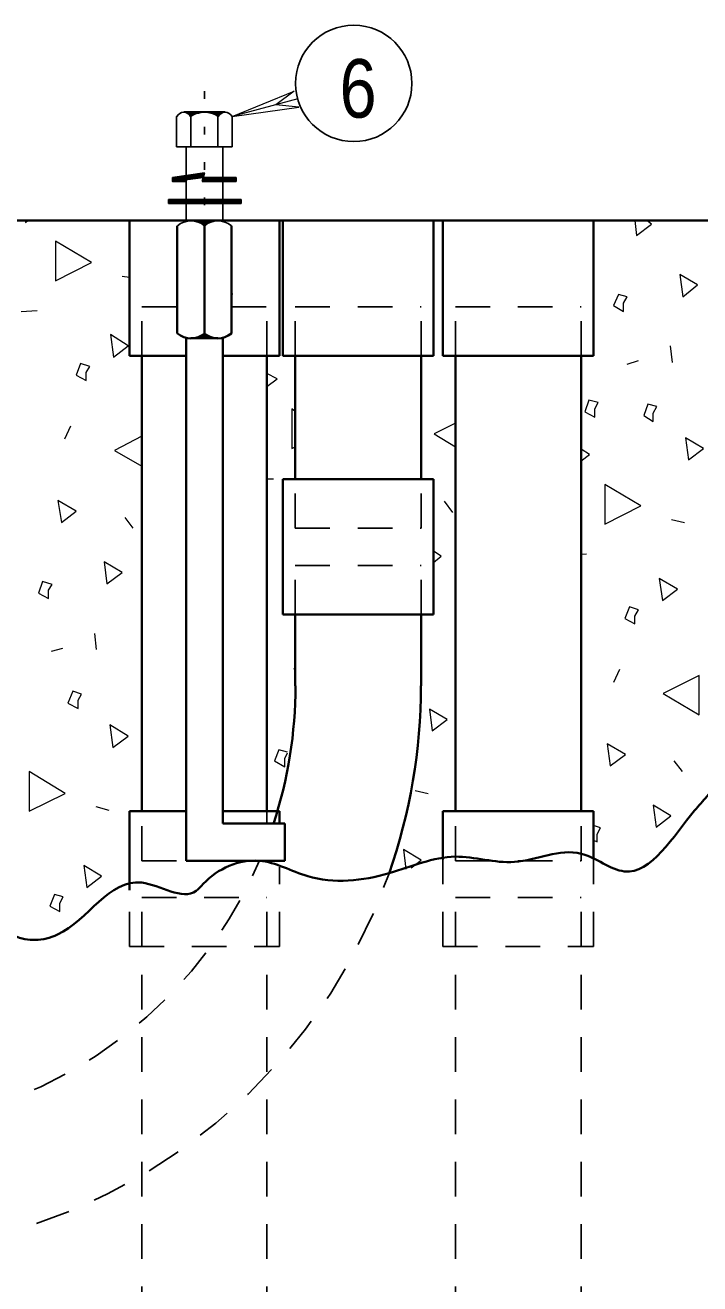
# Model space of a CAD drawing. Extents: x 312583 to 312854, y 144419 to 144597.
# Drawn here: x 312689.79 to 312698.55, y 144530.8 to 144547.14 of the extents above; entities that cross this region are included whole.
import ezdxf

# ---------------------------------------------------------------- set-up
doc = ezdxf.new("R2010")
doc.units = 0
doc.header["$LTSCALE"] = 0.3
doc.linetypes.add('DOTTED', pattern=[1.5, 0.3, -1.2])
doc.linetypes.add('SHORT_DASHED', pattern=[2.7, 1.5, -1.2])
doc.layers.add('1', color=7, linetype='Continuous', lineweight=25)
doc.layers.add('2', color=7, linetype='Continuous', lineweight=13)

msp = doc.modelspace()

# ---------------------------------------------------------------- linework, layer by layer
at = {"layer": '1', "linetype": 'DOTTED'}
msp.add_line((312692.1154, 144546.2789), (312692.1154, 144544.5999), dxfattribs=at)
at = {"layer": '1'}
for p, q in [((312691.7551, 144545.9493), (312691.7551, 144545.5583)), ((312691.8471, 144546.0106), (312692.3837, 144546.0106)), ((312691.9391, 144545.9493), (312691.9391, 144545.5583)), ((312692.2917, 144545.9493), (312692.2917, 144545.5583)), ((312692.4757, 144545.9493), (312692.4757, 144545.5583)), ((312691.7551, 144545.5583), (312692.4757, 144545.5583)), ((312691.8777, 144545.5583), (312691.8777, 144544.5999)), ((312692.3531, 144545.5583), (312692.3531, 144544.5999)), ((312691.7014, 144545.1596), (312691.7014, 144545.1059)), ((312692.0847, 144545.1059), (312692.5294, 144545.1059)), ((312692.1001, 144545.1596), (312692.5294, 144545.1596)), ((312692.5294, 144545.1596), (312692.5294, 144545.1059)), ((312691.6477, 144544.8759), (312692.5907, 144544.8759)), ((312691.6477, 144544.8759), (312691.6477, 144544.8223)), ((312692.5907, 144544.8759), (312692.5907, 144544.8223)), ((312691.6477, 144544.8683), (312692.5907, 144544.8683)), ((312691.6477, 144544.8529), (312692.5907, 144544.8529)), ((312691.6477, 144544.8376), (312692.5907, 144544.8376)), ((312691.6477, 144544.8223), (312692.5907, 144544.8223)), ((312691.8777, 144544.5999), (312692.3531, 144544.5999)), ((312691.9391, 144544.5999), (312692.2917, 144544.5999))]:
    msp.add_line(p, q, dxfattribs=at)
at = {"layer": '1', "lineweight": 40}
for p, q in [((312656.9791, 144544.5999), (312705.5321, 144544.5999)), ((312691.1417, 144542.8443), (312691.1417, 144544.5999)), ((312692.1154, 144544.5999), (312692.1154, 144543.0743)), ((312693.0891, 144542.8443), (312693.0891, 144544.5999)), ((312693.1351, 144542.8443), (312693.1351, 144544.5999)), ((312695.0901, 144542.8443), (312695.0901, 144544.5999)), ((312695.2127, 144542.8443), (312695.2127, 144544.5999)), ((312697.1677, 144542.8443), (312697.1677, 144544.5999)), ((312691.7627, 144544.5309), (312691.7627, 144543.1356)), ((312692.4681, 144544.5309), (312692.4681, 144543.1356)), ((312691.8777, 144543.0743), (312691.8777, 144536.2893)), ((312691.9391, 144543.0743), (312692.2917, 144543.0743)), ((312692.3531, 144543.0743), (312692.3531, 144536.7723)), ((312691.1417, 144542.8443), (312691.8777, 144542.8443)), ((312691.3027, 144536.9333), (312691.3027, 144542.8443)), ((312692.3531, 144542.8443), (312693.0891, 144542.8443)), ((312692.9281, 144536.9333), (312692.9281, 144542.8443)), ((312693.1351, 144542.8443), (312695.0901, 144542.8443)), ((312693.2961, 144541.2419), (312693.2961, 144542.8443)), ((312694.9291, 144541.2419), (312694.9291, 144542.8443)), ((312695.2127, 144542.8443), (312697.1677, 144542.8443)), ((312695.3737, 144536.9333), (312695.3737, 144542.8443)), ((312697.0067, 144536.9333), (312697.0067, 144542.8443)), ((312693.1351, 144539.4863), (312693.1351, 144541.2419)), ((312693.1351, 144541.2419), (312695.0901, 144541.2419)), ((312695.0901, 144539.4863), (312695.0901, 144541.2419)), ((312693.1351, 144539.4863), (312695.0901, 144539.4863)), ((312693.2961, 144538.5586), (312693.2961, 144539.4863)), ((312694.9291, 144538.5586), (312694.9291, 144539.4863)), ((312691.1417, 144536.9333), (312691.8777, 144536.9333)), ((312691.1417, 144535.9059), (312691.1417, 144536.9333)), ((312692.3531, 144536.9333), (312693.0891, 144536.9333)), ((312693.0891, 144536.7723), (312693.0891, 144536.9333)), ((312695.2127, 144536.9333), (312697.1677, 144536.9333)), ((312695.2127, 144536.3046), (312695.2127, 144536.9333)), ((312697.1677, 144536.3123), (312697.1677, 144536.9333)), ((312692.3531, 144536.7723), (312693.1581, 144536.7723)), ((312693.1581, 144536.7723), (312693.1581, 144536.2893)), ((312691.8777, 144536.2893), (312693.1581, 144536.2893))]:
    msp.add_line(p, q, dxfattribs=at)
at = {"layer": '1', "lineweight": 13}
msp.add_line((312692.4681, 144543.6493), (312692.4834, 144543.6493), dxfattribs=at)
at = {"layer": '1', "linetype": 'SHORT_DASHED'}
for p, q in [((312691.3027, 144542.8443), (312691.3027, 144543.4806)), ((312691.3027, 144543.4806), (312691.7627, 144543.4806)), ((312692.4681, 144543.4806), (312692.9281, 144543.4806)), ((312692.9281, 144542.8443), (312692.9281, 144543.4806)), ((312693.2961, 144543.4806), (312694.9291, 144543.4806)), ((312693.2961, 144542.8443), (312693.2961, 144543.4806)), ((312694.9291, 144542.8443), (312694.9291, 144543.4806)), ((312695.3737, 144543.4806), (312697.0067, 144543.4806)), ((312695.3737, 144542.8443), (312695.3737, 144543.4806)), ((312697.0067, 144542.8443), (312697.0067, 144543.4806)), ((312693.2961, 144540.6056), (312693.2961, 144541.2419)), ((312694.9291, 144540.6056), (312694.9291, 144541.2419)), ((312693.2961, 144540.6056), (312694.9291, 144540.6056)), ((312693.2961, 144540.1226), (312694.9291, 144540.1226)), ((312693.2961, 144539.4863), (312693.2961, 144540.1226)), ((312694.9291, 144539.4863), (312694.9291, 144540.1226)), ((312691.3027, 144536.2893), (312691.3027, 144536.9333)), ((312692.9281, 144536.7723), (312692.9281, 144536.9333)), ((312695.3737, 144536.2893), (312695.3737, 144536.9333)), ((312697.0067, 144536.2893), (312697.0067, 144536.9333)), ((312691.3027, 144536.2893), (312691.8777, 144536.2893)), ((312692.3531, 144536.2893), (312692.9281, 144536.2893)), ((312695.2127, 144535.1776), (312695.2127, 144536.3046)), ((312695.3737, 144536.2893), (312697.0067, 144536.2893)), ((312697.1677, 144535.1776), (312697.1677, 144536.3123)), ((312693.0891, 144535.1776), (312693.0891, 144536.2049)), ((312691.1417, 144535.1776), (312691.1417, 144535.9059)), ((312691.3027, 144535.1776), (312691.3027, 144535.8139)), ((312691.3027, 144535.8139), (312692.9281, 144535.8139)), ((312692.9281, 144535.1776), (312692.9281, 144535.8139)), ((312695.3737, 144535.8139), (312697.0067, 144535.8139)), ((312695.3737, 144535.1776), (312695.3737, 144535.8139)), ((312697.0067, 144535.1776), (312697.0067, 144535.8139)), ((312691.1417, 144535.1776), (312693.0891, 144535.1776)), ((312691.3027, 144523.8309), (312691.3027, 144535.1776)), ((312692.9281, 144523.8309), (312692.9281, 144535.1776)), ((312695.2127, 144535.1776), (312697.1677, 144535.1776)), ((312695.3737, 144523.8309), (312695.3737, 144535.1776)), ((312697.0067, 144523.8309), (312697.0067, 144535.1776))]:
    msp.add_line(p, q, dxfattribs=at)
at = {"layer": '1'}
for points in [[(312691.8701, 144546.0029), (312692.0694, 144546.0029), (312692.0387, 144545.9953), (312692.0157, 144545.9953), (312691.9774, 144545.9799), (312691.9391, 144545.9569), (312691.9237, 144545.9799), (312691.9084, 144545.9876), (312691.8777, 144546.0029), (312692.0541, 144546.0029), (312692.0081, 144545.9953), (312691.9697, 144545.9799), (312691.9391, 144545.9569), (312691.9084, 144545.9876), (312691.8931, 144546.0029), (312692.0311, 144546.0029), (312691.9851, 144545.9876), (312691.9391, 144545.9646), (312691.9007, 144545.9953), (312692.0157, 144546.0029), (312691.9391, 144545.9723), (312691.9084, 144545.9953), (312692.0004, 144545.9953), (312691.9391, 144545.9723), (312691.9161, 144545.9953), (312691.9927, 144545.9953), (312691.9391, 144545.9799), (312691.9237, 144545.9953), (312691.9697, 144545.9953), (312691.9391, 144545.9799), (312691.9314, 144545.9876), (312691.9544, 144545.9876), (312691.9391, 144545.9876)], [(312692.3607, 144546.0029), (312692.1614, 144546.0029), (312692.1997, 144545.9953), (312692.2151, 144545.9953), (312692.2534, 144545.9799), (312692.2917, 144545.9569), (312692.3071, 144545.9799), (312692.3224, 144545.9876), (312692.3531, 144546.0029), (312692.1767, 144546.0029), (312692.2304, 144545.9953), (312692.2611, 144545.9799), (312692.2917, 144545.9569), (312692.3224, 144545.9876), (312692.3377, 144546.0029), (312692.1997, 144546.0029), (312692.2457, 144545.9876), (312692.2917, 144545.9646), (312692.3301, 144545.9953), (312692.2151, 144546.0029), (312692.2917, 144545.9723), (312692.3224, 144545.9953), (312692.2304, 144545.9953), (312692.2994, 144545.9723), (312692.3147, 144545.9953), (312692.2457, 144545.9953), (312692.2917, 144545.9799), (312692.3071, 144545.9953), (312692.2611, 144545.9953), (312692.2917, 144545.9799), (312692.2994, 144545.9876), (312692.2764, 144545.9876), (312692.2917, 144545.9876)], [(312691.7014, 144545.1596), (312692.1154, 144545.2209), (312692.0847, 144545.1059)], [(312691.8777, 144545.1059), (312691.7014, 144545.1136), (312691.7091, 144545.1596), (312692.1077, 144545.2056), (312692.0924, 144545.1673), (312691.8777, 144545.1366), (312691.8701, 144545.1136), (312691.7091, 144545.1213), (312691.7167, 144545.1519), (312692.0924, 144545.1979), (312692.0847, 144545.1749), (312691.8624, 144545.1366), (312691.8624, 144545.1213), (312691.7167, 144545.1213), (312691.7167, 144545.1366), (312692.0771, 144545.1903), (312692.0771, 144545.1826), (312691.8701, 144545.1443), (312691.8547, 144545.1366), (312691.8087, 144545.1289), (312691.7244, 144545.1289), (312692.0694, 144545.1826), (312691.7781, 144545.1289)], [(312692.1001, 144545.1596), (312691.7014, 144545.1059), (312691.8777, 144545.1059)], [(312692.0924, 144545.1136), (312692.5217, 144545.1136), (312692.5217, 144545.1596), (312692.1077, 144545.1519), (312692.0924, 144545.1213), (312692.5141, 144545.1213), (312692.5141, 144545.1443), (312692.1077, 144545.1443), (312692.1001, 144545.1213), (312692.5064, 144545.1289), (312692.4987, 144545.1366), (312692.4987, 144545.1443), (312692.1154, 144545.1366), (312692.1077, 144545.1289), (312692.4987, 144545.1289)], [(312691.9851, 144544.5923), (312692.2457, 144544.5923), (312692.2151, 144544.5923), (312692.1921, 144544.5846), (312692.1614, 144544.5693), (312692.1461, 144544.5616), (312692.1154, 144544.5463), (312692.1154, 144544.5386), (312692.0694, 144544.5693), (312692.0234, 144544.5846), (312692.0004, 144544.5923), (312692.2304, 144544.5923), (312692.2074, 144544.5923), (312692.1921, 144544.5846), (312692.1614, 144544.5769), (312692.1307, 144544.5616), (312692.1231, 144544.5539), (312692.1154, 144544.5463), (312692.0694, 144544.5693), (312692.0234, 144544.5923), (312692.1921, 144544.5923), (312692.1537, 144544.5769), (312692.1154, 144544.5539), (312692.0387, 144544.5846), (312692.1767, 144544.5923), (312692.1154, 144544.5463), (312692.0541, 144544.5846), (312692.1691, 144544.5846), (312692.1231, 144544.5616), (312692.0771, 144544.5846), (312692.1461, 144544.5846), (312692.1154, 144544.5693), (312692.0771, 144544.5769), (312692.1001, 144544.5616), (312692.1077, 144544.5769), (312692.1154, 144544.5539), (312692.1307, 144544.5769), (312692.1384, 144544.5769), (312692.1537, 144544.5769)]]:
    msp.add_lwpolyline(points, dxfattribs=at)
at = {"layer": '1', "lineweight": 40}
msp.add_lwpolyline([(312691.9851, 144543.0743), (312692.2457, 144543.0743), (312692.2151, 144543.0819), (312692.1921, 144543.0896), (312692.1614, 144543.0973), (312692.1461, 144543.1126), (312692.1154, 144543.1279), (312692.1154, 144543.1279), (312692.0694, 144543.0973), (312692.0234, 144543.0819), (312692.0004, 144543.0743), (312692.2304, 144543.0743), (312692.2074, 144543.0743), (312692.1921, 144543.0819), (312692.1614, 144543.0896), (312692.1307, 144543.1049), (312692.1231, 144543.1126), (312692.1154, 144543.1279), (312692.0694, 144543.0973), (312692.0234, 144543.0743), (312692.1921, 144543.0743), (312692.1537, 144543.0896), (312692.1154, 144543.1126), (312692.0387, 144543.0819), (312692.1767, 144543.0819), (312692.1154, 144543.1203), (312692.0541, 144543.0819), (312692.1691, 144543.0819), (312692.1231, 144543.1049), (312692.0771, 144543.0896), (312692.1461, 144543.0896), (312692.1154, 144543.0973), (312692.0771, 144543.0896), (312692.1001, 144543.1049), (312692.1077, 144543.0896), (312692.1154, 144543.1126), (312692.1307, 144543.0973), (312692.1384, 144543.0896), (312692.1537, 144543.0896)], dxfattribs=at)
at = {"layer": '1'}
for centre, radius, start, end in [((312691.8474, 144545.9078), 0.0993, 25.60064, 154.39936), ((312692.116, 144545.6945), 0.3126, 55.04559, 124.95441), ((312692.3847, 144545.9078), 0.0993, 25.60064, 154.39936), ((312691.9412, 144544.3253), 0.272, 50.00693, 129.99306), ((312692.2908, 144544.3253), 0.272, 50.00694, 129.99307)]:
    msp.add_arc(centre, radius, start, end, dxfattribs=at)
at = {"layer": '1', "lineweight": 40}
for centre, radius, start, end in [((312691.9412, 144543.3426), 0.272, 230.00694, 309.99307), ((312692.2908, 144543.3426), 0.272, 230.00693, 309.99306), ((312687.548, 144538.5599), 5.75, 341.8604, 0), ((312687.548, 144538.5599), 7.3792, 340.73599, 0)]:
    msp.add_arc(centre, radius, start, end, dxfattribs=at)
at = {"layer": '1', "linetype": 'SHORT_DASHED'}
for radius, end in [(5.75, 336.76867), (7.3792, 340.7336)]:
    msp.add_arc((312687.548, 144538.5599), radius, 270, end, dxfattribs=at)
at = {"layer": '1', "lineweight": 40}
msp.add_spline([(312699.3604, 144544.5999), (312699.8664, 144543.7259), (312700.4721, 144542.8443), (312700.1194, 144541.7709), (312699.5521, 144541.3263), (312699.2991, 144540.4139), (312699.1764, 144538.1983), (312698.6397, 144537.1249), (312698.4787, 144536.9409), (312697.5664, 144536.1513), (312697.0067, 144536.3813), (312696.1404, 144536.2739), (312695.3737, 144536.3429), (312694.5151, 144536.1283), (312693.4571, 144536.0899), (312692.8284, 144536.2893), (312692.1001, 144535.9903), (312692.0081, 144535.8983), (312691.3027, 144536.0056), (312690.2064, 144535.3309), (312689.9227, 144535.2619), (312688.8571, 144535.8293), (312687.2624, 144535.9059), (312686.9251, 144535.4459)], degree=3, dxfattribs=at)
at = {"layer": '2'}
for p, q in [((312692.4757, 144545.9493), (312693.2807, 144546.2789)), ((312693.3267, 144546.1793), (312692.4757, 144545.9493)), ((312693.2807, 144546.2789), (312693.0431, 144546.1026)), ((312692.4757, 144545.9493), (312693.3421, 144546.0719)), ((312693.3421, 144546.0719), (312693.0431, 144546.1026)), ((312689.7924, 144544.5769), (312689.8231, 144544.5999)), ((312689.7924, 144544.5999), (312689.7924, 144544.5769)), ((312697.7044, 144544.5999), (312697.7274, 144544.4083)), ((312691.0497, 144543.8793), (312691.1417, 144543.8639)), ((312689.7387, 144543.4193), (312689.9457, 144543.4346)), ((312698.1644, 144542.9746), (312698.1874, 144542.7599)), ((312697.6047, 144542.7369), (312697.7504, 144542.7829)), ((312693.2961, 144542.1236), (312693.2501, 144542.1543)), ((312690.3751, 144541.9319), (312690.2984, 144541.7633)), ((312692.9281, 144541.2496), (312693.0124, 144541.2496)), ((312695.2281, 144540.9583), (312695.3354, 144540.8126)), ((312691.0804, 144540.7436), (312691.1877, 144540.6056)), ((312698.1797, 144540.7206), (312698.3484, 144540.6823)), ((312697.0067, 144540.2683), (312697.0757, 144540.2759)), ((312690.6894, 144539.2409), (312690.7124, 144539.0339)), ((312690.1297, 144539.0109), (312690.2754, 144539.0493)), ((312697.5051, 144538.7733), (312697.4284, 144538.6046)), ((312693.1581, 144537.6156), (312693.1964, 144537.6923)), ((312698.2104, 144537.5849), (312698.3177, 144537.4469)), ((312694.8524, 144537.2016), (312695.0211, 144537.1633)), ((312690.7047, 144536.9946), (312690.8734, 144536.9486))]:
    msp.add_line(p, q, dxfattribs=at)
for points in [[(312697.7274, 144544.4083), (312697.9191, 144544.5539), (312697.8577, 144544.5999)], [(312692.9281, 144542.4456), (312693.0584, 144542.5453), (312692.9281, 144542.6143)], [(312693.2501, 144542.1543), (312693.2501, 144541.6406), (312693.2961, 144541.6636)], [(312695.3737, 144541.9703), (312695.0977, 144541.8323), (312695.3737, 144541.6636)], [(312691.3027, 144541.8016), (312690.9501, 144541.6176), (312691.3027, 144541.4106)], [(312697.0067, 144541.4796), (312697.1141, 144541.5639), (312697.0067, 144541.6329)], [(312695.0901, 144540.1609), (312695.1897, 144540.2453), (312695.0901, 144540.3066)], [(312693.2961, 144538.7733), (312693.2807, 144538.7886), (312693.2961, 144538.6813)], [(312693.1964, 144537.6999), (312693.0814, 144537.7306), (312693.0277, 144537.5849), (312693.1581, 144537.5083), (312693.1581, 144537.6156)], [(312697.2137, 144536.6343), (312697.2597, 144536.7186), (312697.1677, 144536.7493)], [(312697.1677, 144536.5576), (312697.2137, 144536.5346), (312697.2137, 144536.6343)], [(312694.7987, 144536.1973), (312694.9291, 144536.2969), (312694.6991, 144536.4349), (312694.7297, 144536.1819)]]:
    msp.add_lwpolyline(points, dxfattribs=at)
for points in [[(312690.1834, 144544.3316), (312690.1834, 144543.8179), (312690.6511, 144544.0556)], [(312698.3254, 144543.6109), (312698.5171, 144543.7643), (312698.2871, 144543.9023)], [(312697.5587, 144543.5266), (312697.6047, 144543.6109), (312697.4897, 144543.6416), (312697.4284, 144543.4959), (312697.5587, 144543.4193)], [(312690.9347, 144542.8289), (312691.1264, 144542.9746), (312690.8964, 144543.1203)], [(312690.5821, 144542.6296), (312690.6281, 144542.7063), (312690.5054, 144542.7446), (312690.4517, 144542.5913), (312690.5821, 144542.5223)], [(312697.1831, 144542.1543), (312697.2291, 144542.2386), (312697.1064, 144542.2693), (312697.0527, 144542.1159), (312697.1831, 144542.0469)], [(312697.9421, 144542.1006), (312697.9881, 144542.1849), (312697.8731, 144542.2156), (312697.8194, 144542.0699), (312697.9421, 144541.9933)], [(312698.4021, 144541.4949), (312698.5937, 144541.6406), (312698.3637, 144541.7786)], [(312697.3134, 144541.1729), (312697.3134, 144540.6593), (312697.7811, 144540.8969)], [(312690.2601, 144540.6823), (312690.4517, 144540.8279), (312690.2141, 144540.9659)], [(312690.8504, 144539.8849), (312691.0497, 144540.0306), (312690.8121, 144540.1686)], [(312690.0914, 144539.8006), (312690.1374, 144539.8773), (312690.0147, 144539.9156), (312689.9611, 144539.7623), (312690.0914, 144539.6933)], [(312698.0647, 144539.6703), (312698.2564, 144539.8159), (312698.0187, 144539.9539)], [(312697.7044, 144539.4633), (312697.7504, 144539.5476), (312697.6354, 144539.5859), (312697.5741, 144539.4326), (312697.7044, 144539.3636)], [(312698.5401, 144538.1829), (312698.5401, 144538.6966), (312698.0724, 144538.4589)], [(312690.4747, 144538.3746), (312690.5207, 144538.4513), (312690.4057, 144538.4896), (312690.3444, 144538.3363), (312690.4747, 144538.2673)], [(312695.0747, 144537.9759), (312695.2664, 144538.1216), (312695.0364, 144538.2596)], [(312690.9271, 144537.7613), (312691.1264, 144537.9069), (312690.8887, 144538.0526)], [(312697.3824, 144537.5236), (312697.5817, 144537.6693), (312697.3441, 144537.8073)], [(312689.8384, 144537.4469), (312689.8384, 144536.9333), (312690.3061, 144537.1633)], [(312697.9804, 144536.7263), (312698.1721, 144536.8719), (312697.9421, 144537.0099)], [(312690.5897, 144535.9443), (312690.7814, 144536.0899), (312690.5514, 144536.2279)], [(312690.2371, 144535.7373), (312690.2831, 144535.8216), (312690.1681, 144535.8523), (312690.1067, 144535.6989), (312690.2371, 144535.6299)]]:
    msp.add_lwpolyline(points, close=True, dxfattribs=at)
at = {"layer": '2', "lineweight": 25}
msp.add_circle((312694.0543, 144546.3812), 0.7557, dxfattribs=at)

# ---------------------------------------------------------------- texts
at = {"layer": '2', "width": 0.85}
msp.add_text('6', height=0.76, dxfattribs=at).set_placement((312693.8707, 144545.9364))

doc.saveas('drawing.dxf')
